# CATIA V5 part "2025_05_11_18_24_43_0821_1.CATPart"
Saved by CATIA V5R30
Part number: 2025_05_11_18_24_43_0821_1
Definition: 2025_05_11_18_24_43_0821
Nomenclature: 2025_05_11_18_24_43_0821
Source: Unknown
Description: PART-2025_05_11_18_24_43_0821-DESC
Bounding box of the stored display mesh (mm): x 240.75 to 266.25, y -12.75 to 12.75, z 0 to 53
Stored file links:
  E:\Bakalarka\Model\Forma_v7\2025_05_11_18_24_43_0821_1.CATPart
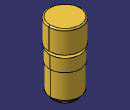
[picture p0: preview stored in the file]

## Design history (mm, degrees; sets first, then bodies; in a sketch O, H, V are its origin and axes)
Body1 "MANIFOLD_SOLID_BREP #148" (main body)
  Solid1: solid without history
